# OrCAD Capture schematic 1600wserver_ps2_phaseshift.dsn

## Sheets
1 PAGE3: size C
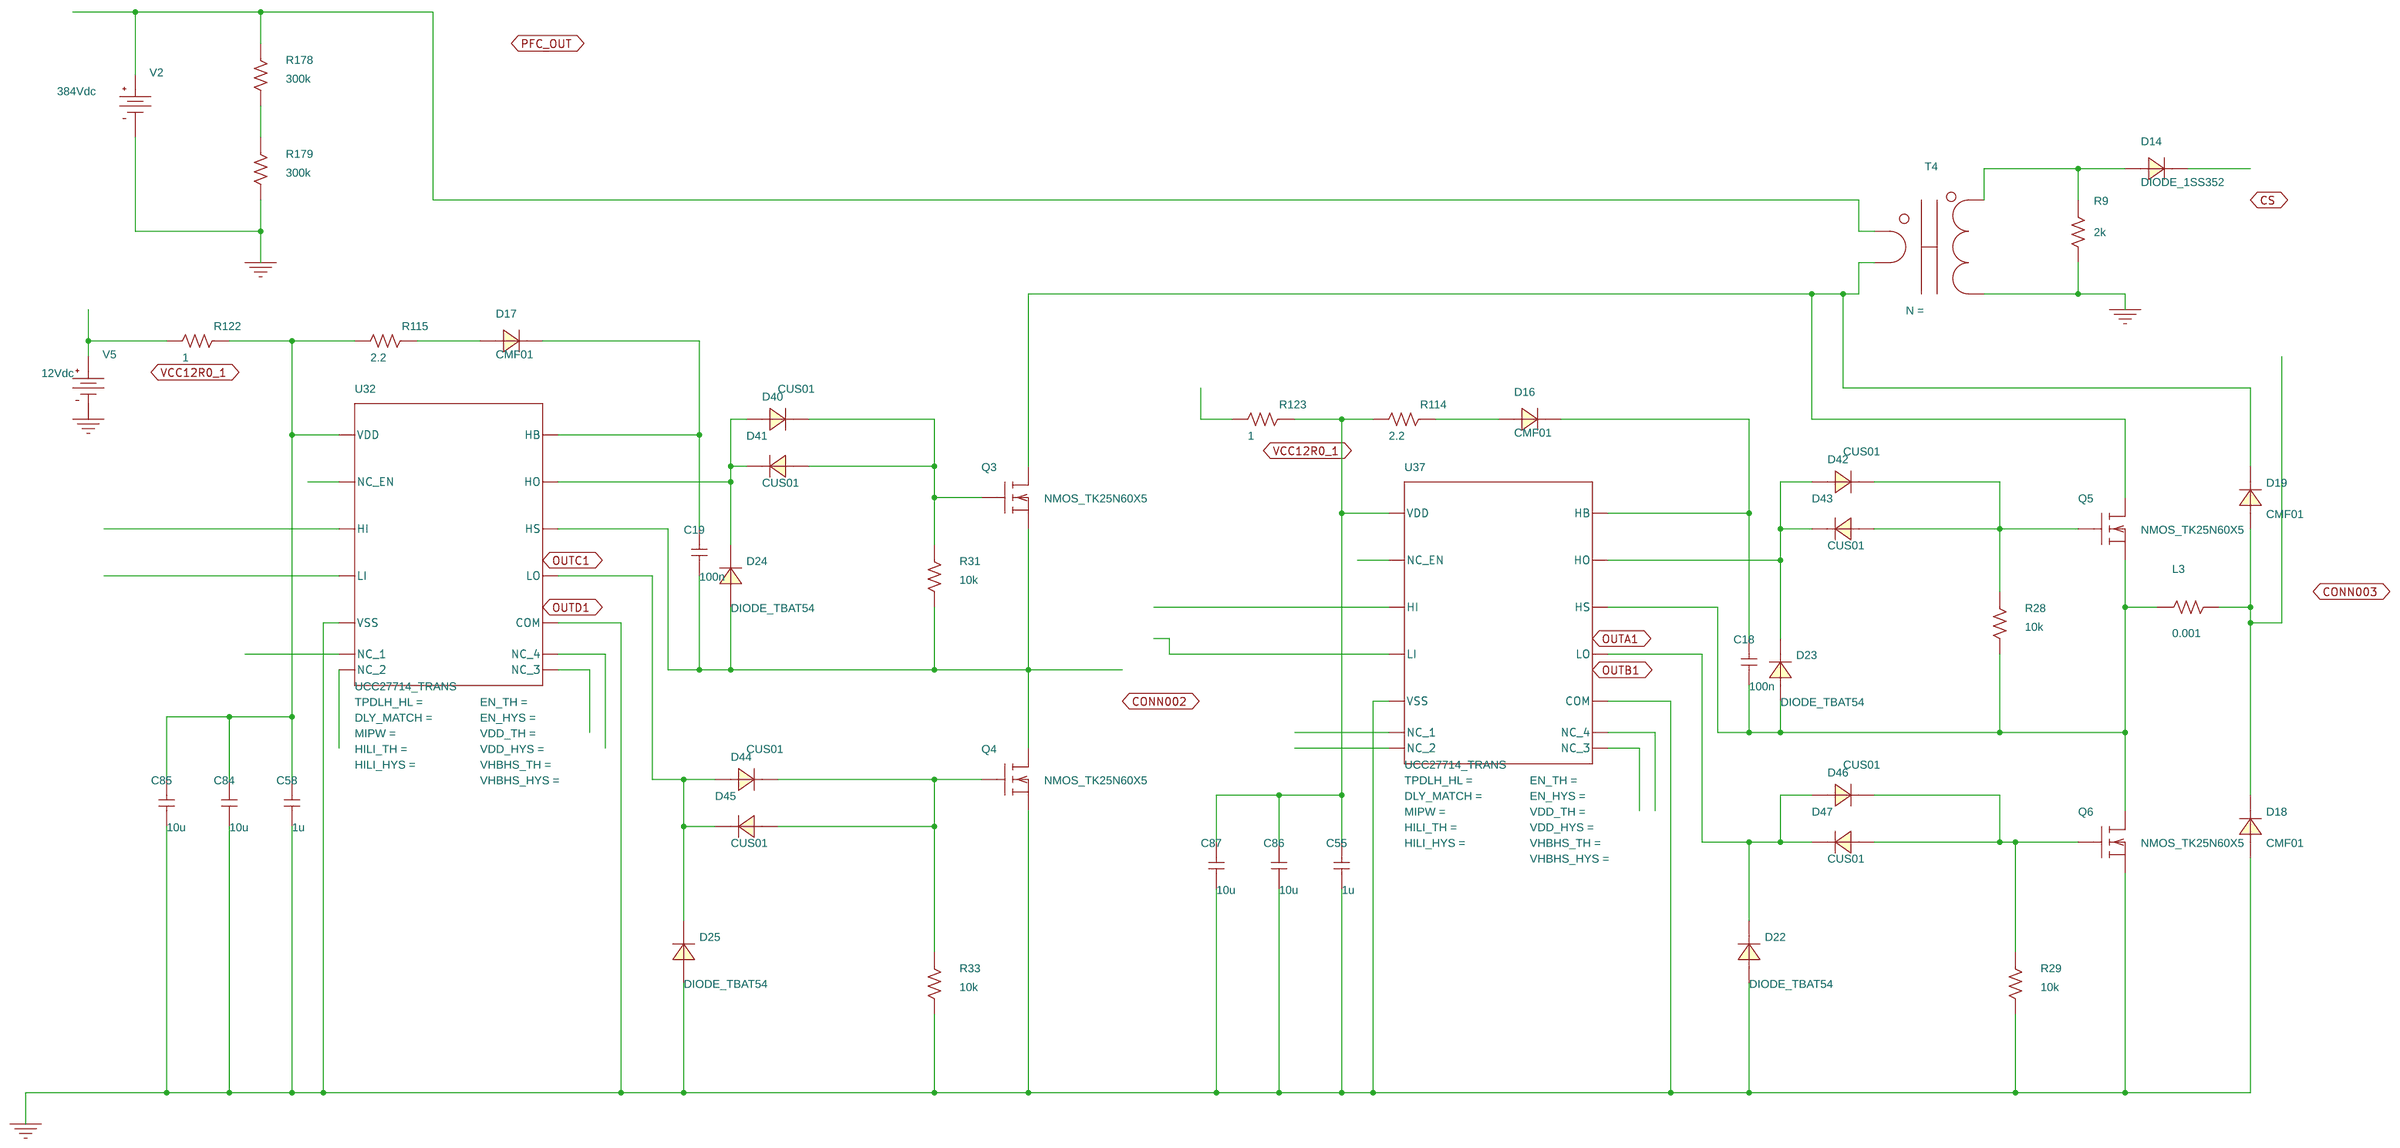
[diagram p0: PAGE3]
2 PAGE2: size C
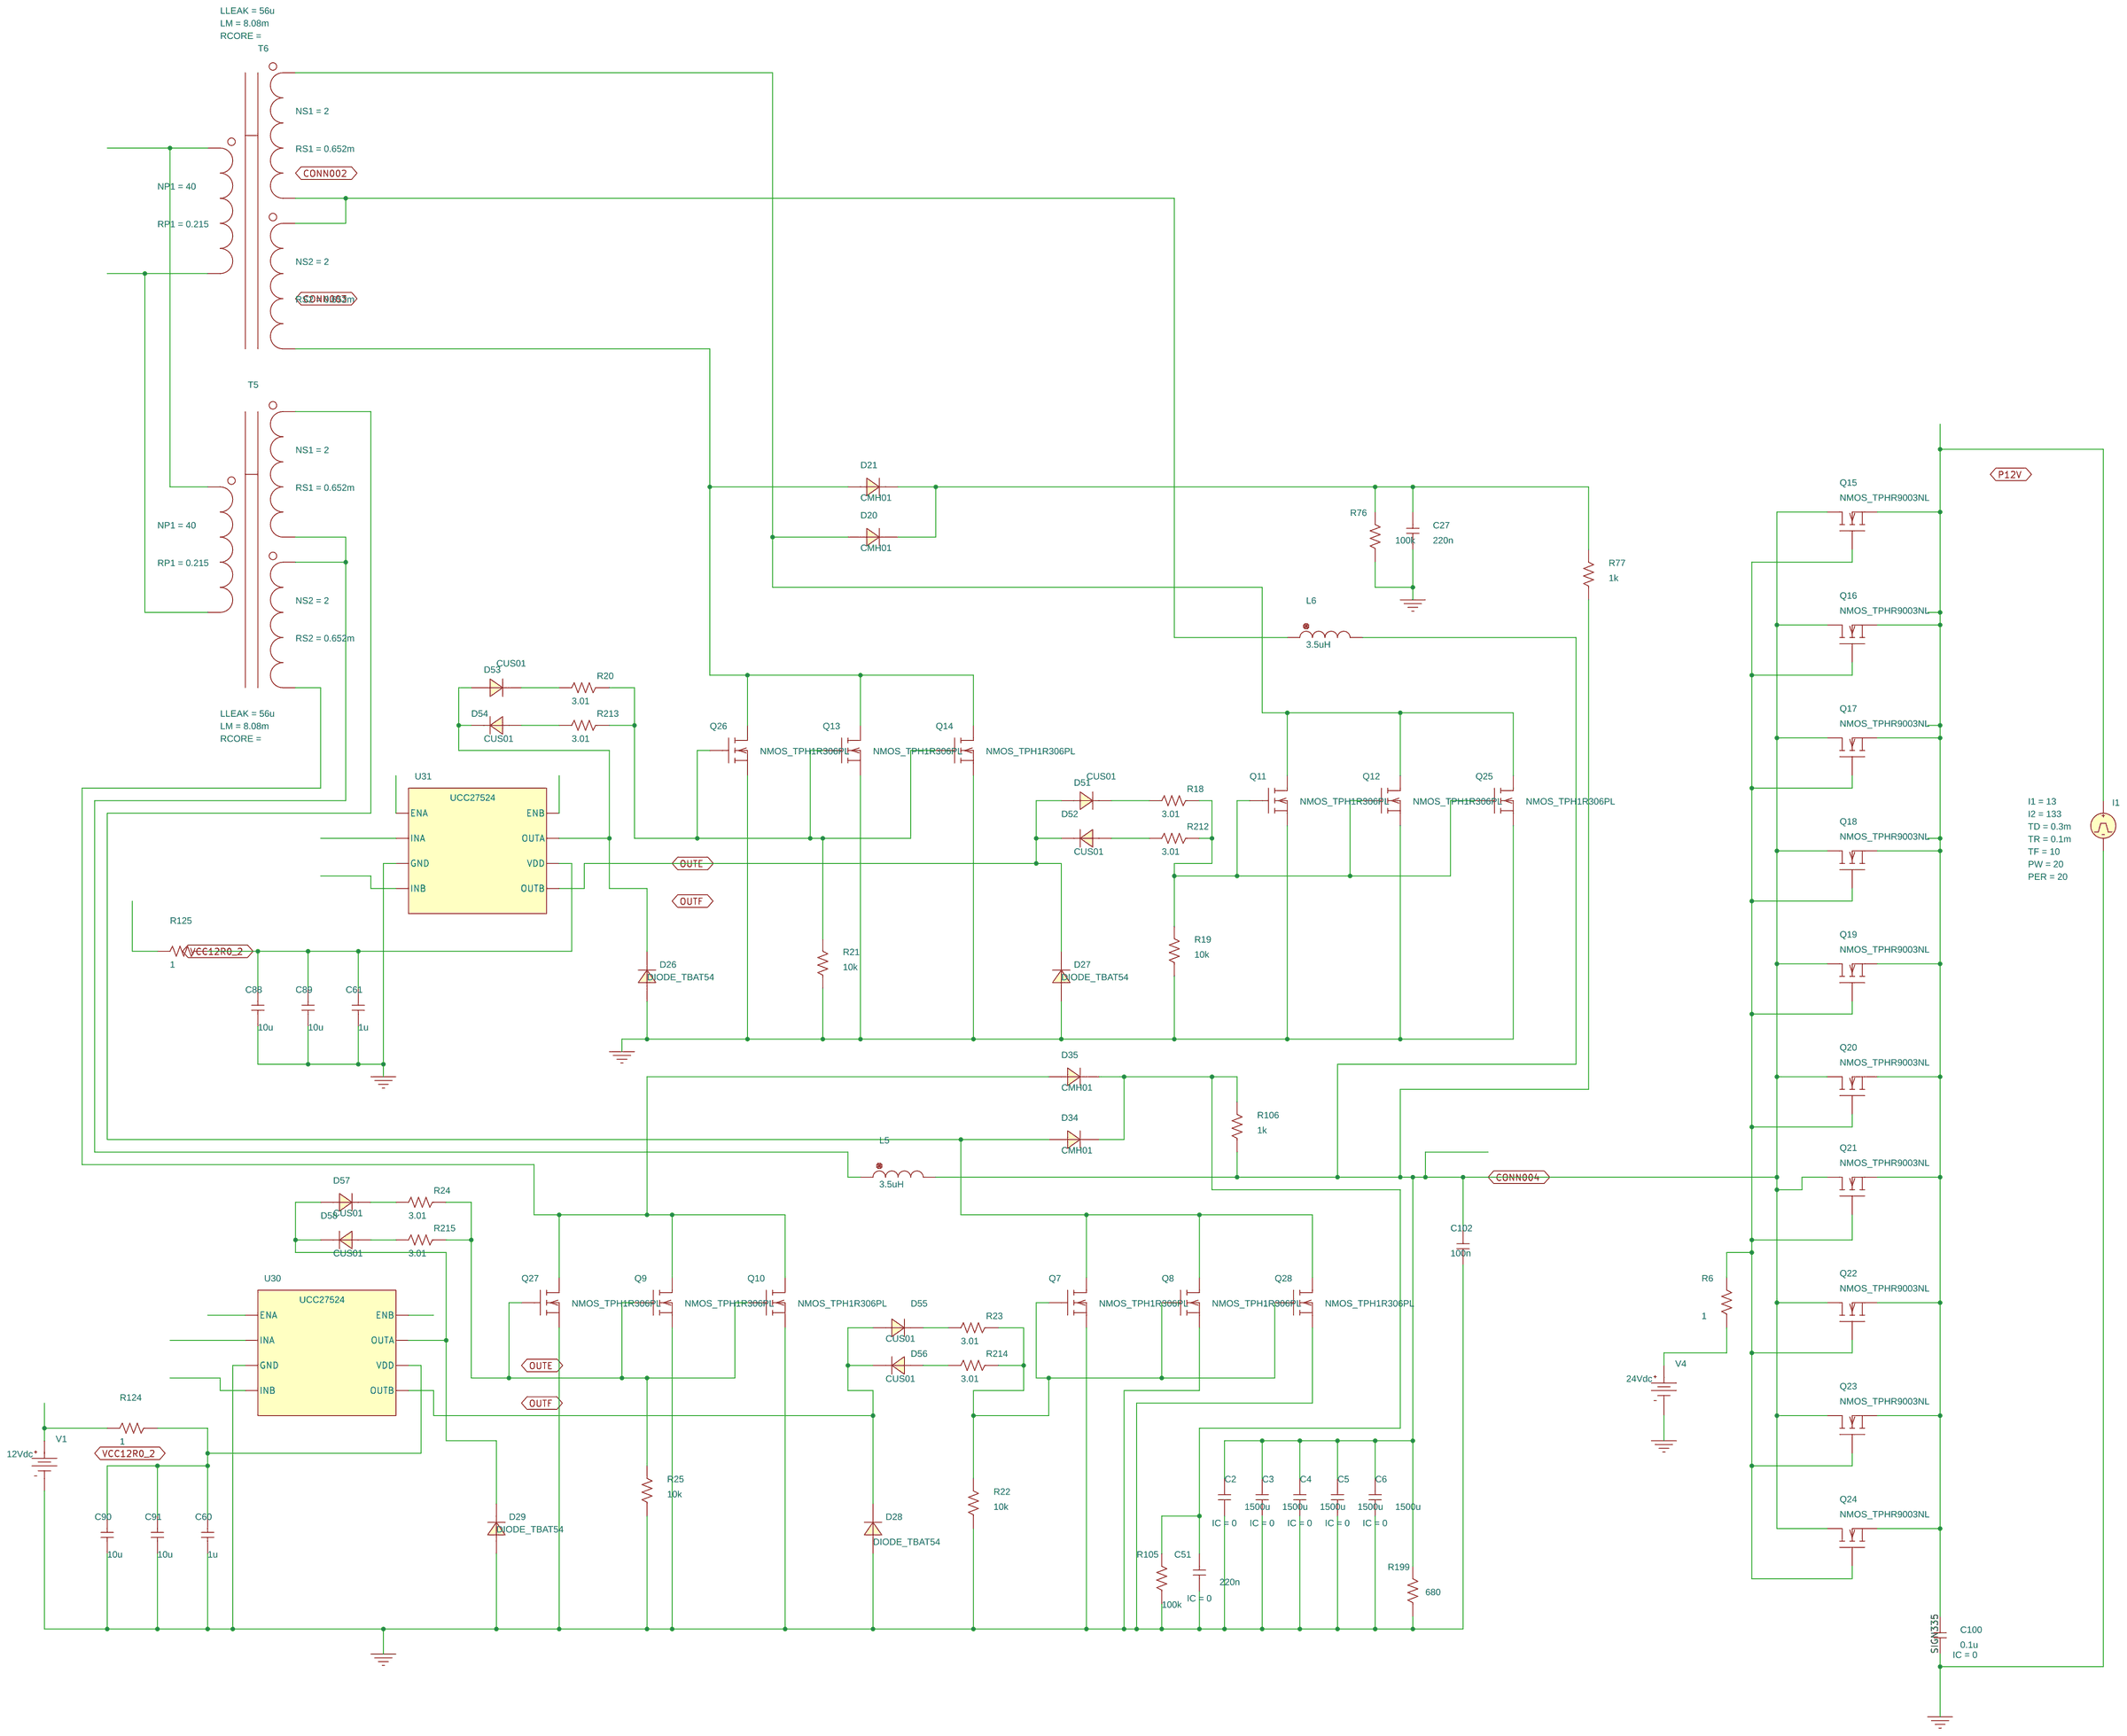
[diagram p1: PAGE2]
3 PAGE1: size C
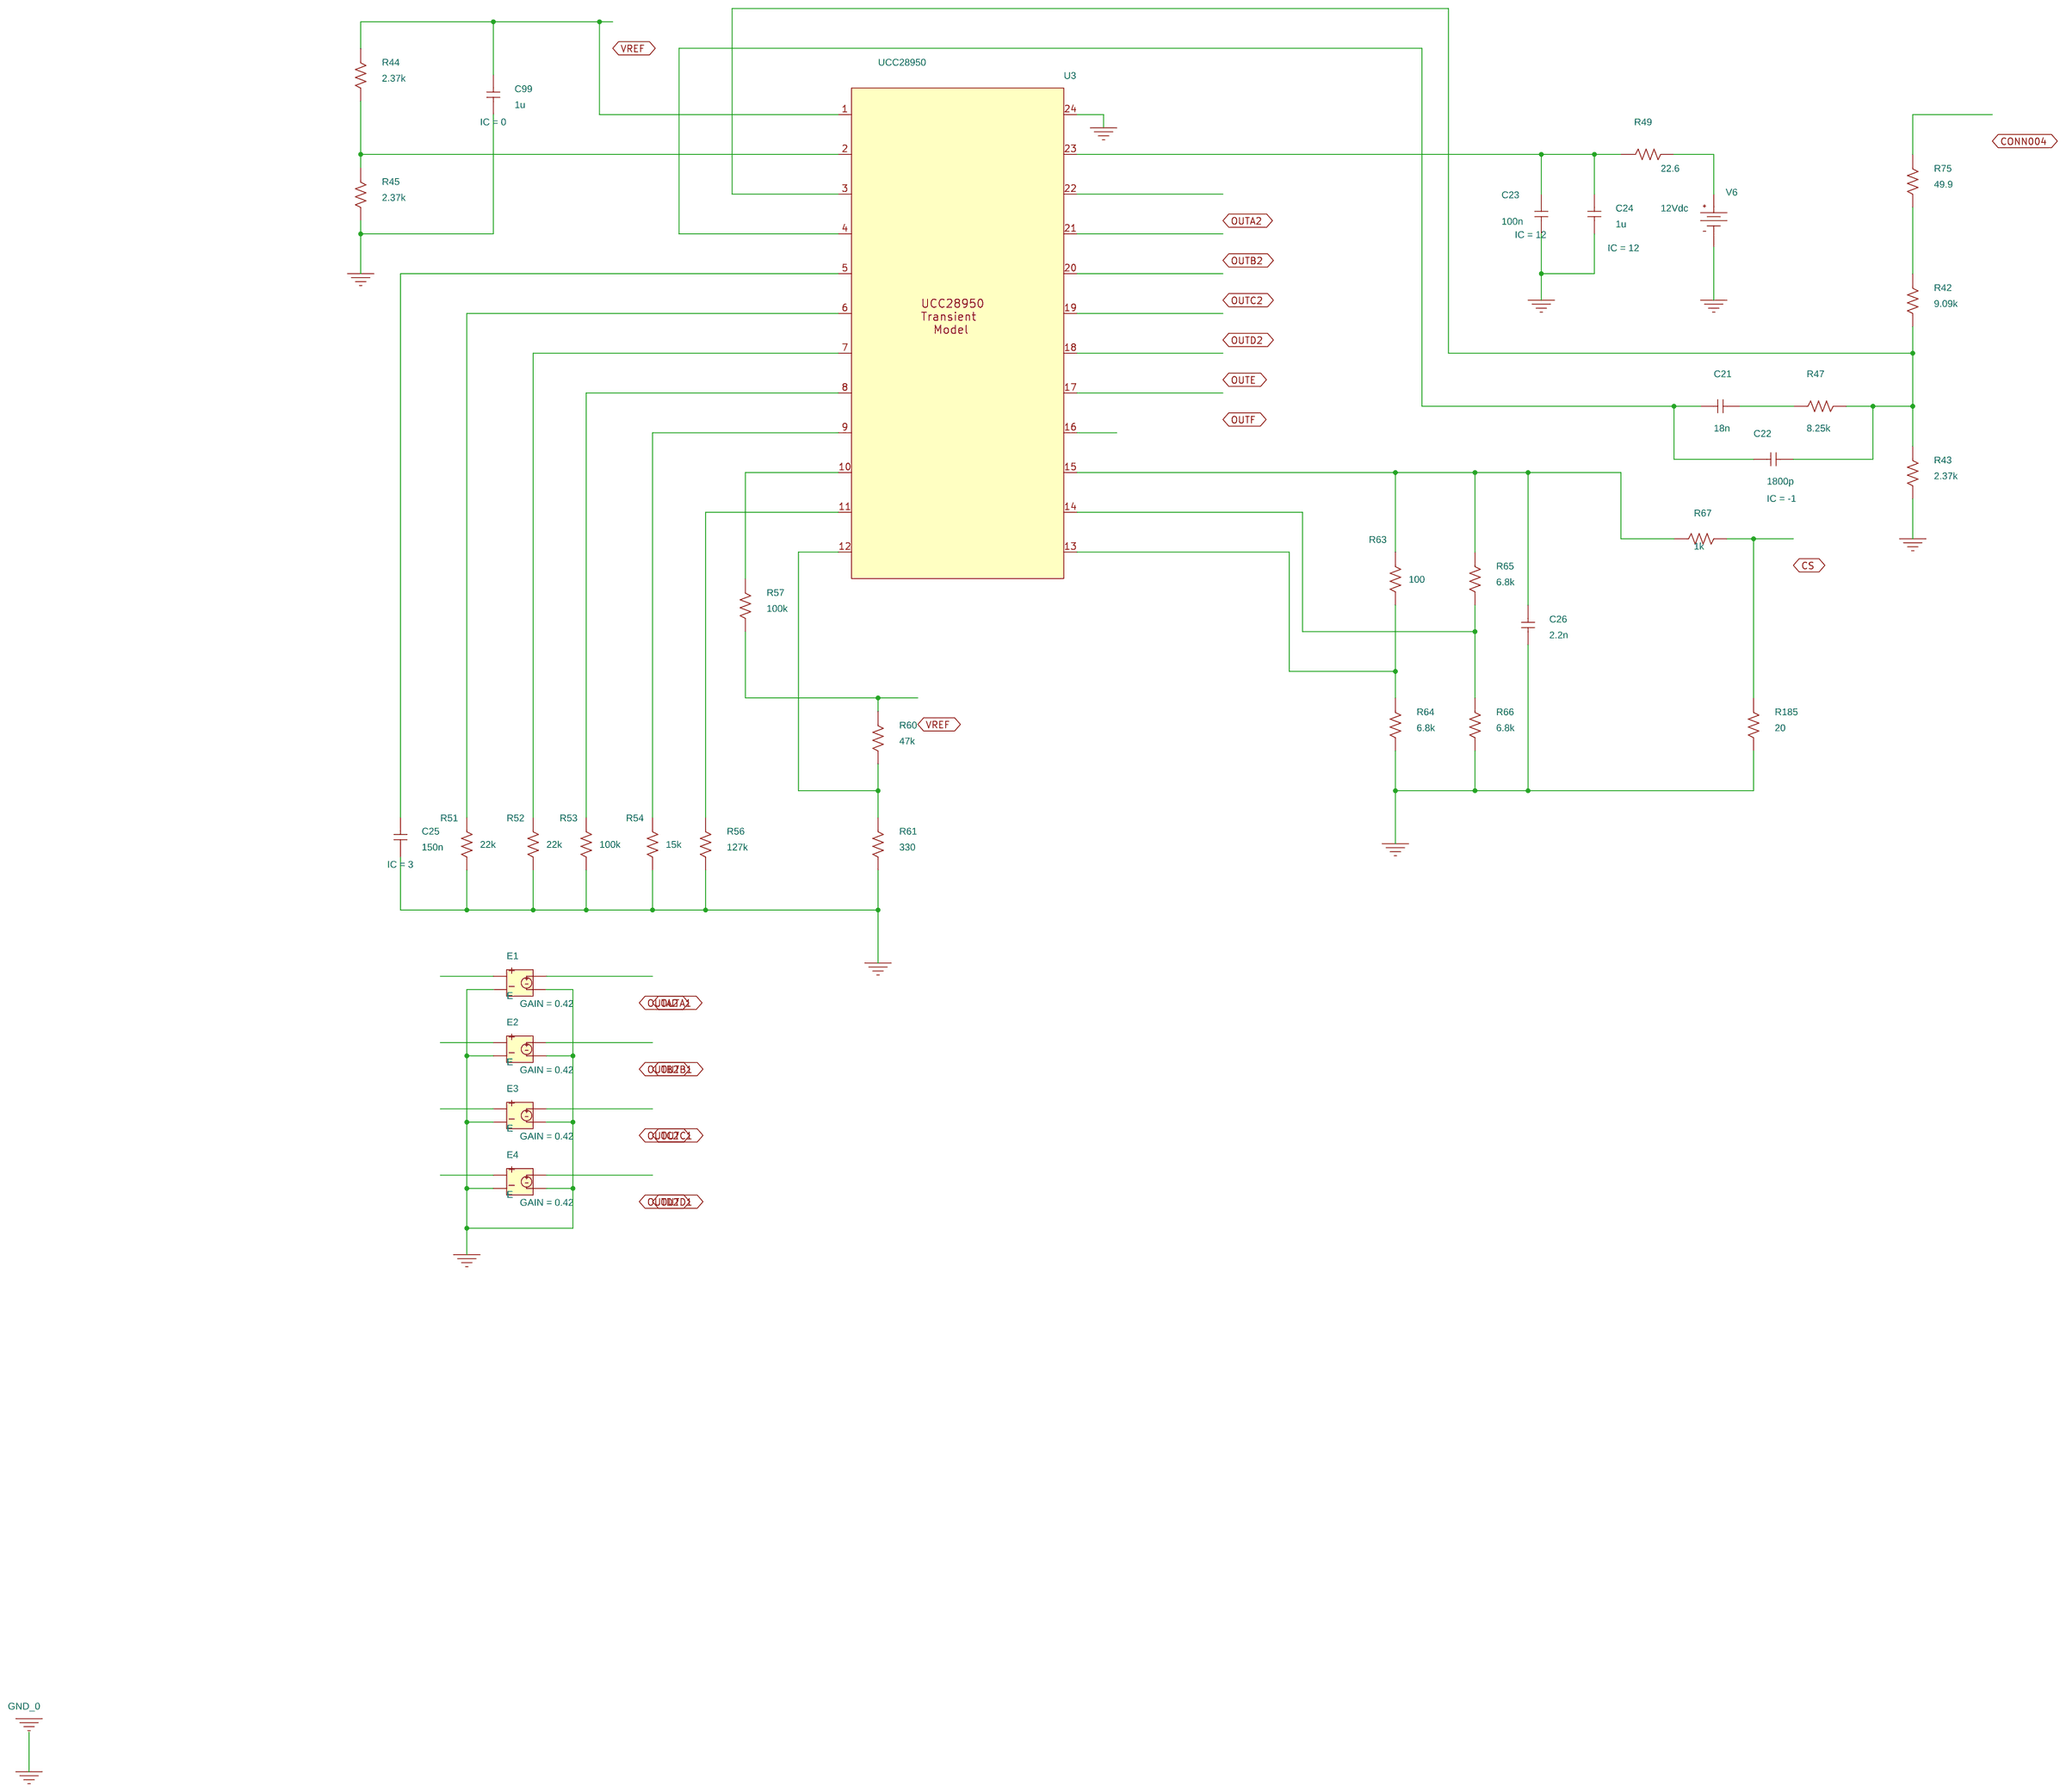
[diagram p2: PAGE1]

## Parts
sheet PAGE1
C21  18n  [RAD/CK05]
C22  1800p  [RAD/CK05]
C23  100n  [RAD/CK05]
C24  1u  [RAD/CK05]
C25  150n  [RAD/CK05]
C26  2.2n  [RAD/CK05]
C99  1u  [RAD/CK05]
E1  E
E2  E
E3  E
E4  E
R42  9.09k  [AX/RC05]
R43  2.37k  [AX/RC05]
R44  2.37k  [AX/RC05]
R45  2.37k  [AX/RC05]
R47  8.25k  [AX/RC05]
R49  22.6  [AX/RC05]
R51  22k  [AX/RC05]
R52  22k  [AX/RC05]
R53  100k  [AX/RC05]
R54  15k  [AX/RC05]
R56  127k  [AX/RC05]
R57  100k  [AX/RC05]
R60  47k  [AX/RC05]
R61  330  [AX/RC05]
R63  100  [AX/RC05]
R64  6.8k  [AX/RC05]
R65  6.8k  [AX/RC05]
R66  6.8k  [AX/RC05]
R67  1k  [AX/RC05]
R75  49.9  [AX/RC05]
R185  20  [AX/RC05]
U3  UCC28950
V6  VDC
sheet PAGE2
C2  1500u  [RAD/CK05]
C3  1500u  [RAD/CK05]
C4  1500u  [RAD/CK05]
C5  1500u  [RAD/CK05]
C6  1500u  [RAD/CK05]
C27  220n  [RAD/CK05]
C51  220n  [RAD/CK05]
C60  1u  [RAD/CK05]
C61  1u  [RAD/CK05]
C88  10u  [RAD/CK05]
C89  10u  [RAD/CK05]
C90  10u  [RAD/CK05]
C91  10u  [RAD/CK05]
C100  0.1u  [RAD/CK05]
C102  100n  [RAD/CK05]
D20  CMH01
D21  CMH01
D26  DIODE_TBAT54
D27  DIODE_TBAT54
D28  DIODE_TBAT54
D29  DIODE_TBAT54
D34  CMH01
D35  CMH01
D51  CUS01
D52  CUS01
D53  CUS01
D54  CUS01
D55  CUS01
D56  CUS01
D57  CUS01
D58  CUS01
I1  IPULSE
L5  3.5uH  [DISC/.350x.175/LS.200x.100/.034]
L6  3.5uH  [DISC/.350x.175/LS.200x.100/.034]
Q7  NMOS_TPH1R306PL
Q8  NMOS_TPH1R306PL
Q9  NMOS_TPH1R306PL
Q10  NMOS_TPH1R306PL
Q11  NMOS_TPH1R306PL
Q12  NMOS_TPH1R306PL
Q13  NMOS_TPH1R306PL
Q14  NMOS_TPH1R306PL
Q15  NMOS_TPHR9003NL
Q16  NMOS_TPHR9003NL
Q17  NMOS_TPHR9003NL
Q18  NMOS_TPHR9003NL
Q19  NMOS_TPHR9003NL
Q20  NMOS_TPHR9003NL
Q21  NMOS_TPHR9003NL
Q22  NMOS_TPHR9003NL
Q23  NMOS_TPHR9003NL
Q24  NMOS_TPHR9003NL
Q25  NMOS_TPH1R306PL
Q26  NMOS_TPH1R306PL
Q27  NMOS_TPH1R306PL
Q28  NMOS_TPH1R306PL
R6  1  [AX/RC05]
R18  3.01  [AX/RC05]
R19  10k  [AX/RC05]
R20  3.01  [AX/RC05]
R21  10k  [AX/RC05]
R22  10k  [AX/RC05]
R23  3.01  [AX/RC05]
R24  3.01  [AX/RC05]
R25  10k  [AX/RC05]
R76  100k  [AX/RC05]
R77  1k  [AX/RC05]
R105  100k  [AX/RC05]
R106  1k  [AX/RC05]
R124  1  [AX/RC05]
R125  1  [AX/RC05]
R199  680  [AX/RC05]
R212  3.01  [AX/RC05]
R213  3.01  [AX/RC05]
R214  3.01  [AX/RC05]
R215  3.01  [AX/RC05]
T5  XFOR_1P2S
T6  XFOR_1P2S
U30  UCC27524
U31  UCC27524
V1  VDC
V4  VDC
sheet PAGE3
C18  100n  [RAD/CK05]
C19  100n  [RAD/CK05]
C55  1u  [RAD/CK05]
C58  1u  [RAD/CK05]
C84  10u  [RAD/CK05]
C85  10u  [RAD/CK05]
C86  10u  [RAD/CK05]
C87  10u  [RAD/CK05]
D14  DIODE_1SS352
D16  CMF01
D17  CMF01
D18  CMF01
D19  CMF01
D22  DIODE_TBAT54
D23  DIODE_TBAT54
D24  DIODE_TBAT54
D25  DIODE_TBAT54
D40  CUS01
D41  CUS01
D42  CUS01
D43  CUS01
D44  CUS01
D45  CUS01
D46  CUS01
D47  CUS01
L3  0.001  [AX/RC05]
Q3  NMOS_TK25N60X5
Q4  NMOS_TK25N60X5
Q5  NMOS_TK25N60X5
Q6  NMOS_TK25N60X5
R9  2k  [AX/RC05]
R28  10k  [AX/RC05]
R29  10k  [AX/RC05]
R31  10k  [AX/RC05]
R33  10k  [AX/RC05]
R114  2.2  [AX/RC05]
R115  2.2  [AX/RC05]
R122  1  [AX/RC05]
R123  1  [AX/RC05]
R178  300k  [AX/RC05]
R179  300k  [AX/RC05]
T4  XFOR_CS
U32  UCC27714_TRANS
U37  UCC27714_TRANS
V2  VDC
V5  VDC

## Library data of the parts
C18 C19 C21 C26 C27 C55 C58 C60 C61 C84-C91 C102 = C_v3
C22 = C_v3: IC: -1
C23 C24 = C_v3: IC: 12
C25 = C_v3: IC: 3
C2-C6 C51 C99 C100 = C_v3: IC: 0
E1-E4 = E: GAIN: 0.42
L3 R6 R9 R18-R25 R28 R29 R31 R33 R42-R45 R47 R49 R51-R54 R56 R57 R60 R61 R63-R67 R75-R77 R105 R106 R114 R115 R122-R125 R178 R179 R185 R199 R212-R215 = R_v3
U3 = UCC28950
V1 V5 V6 = VDC: DC: 12Vdc
D20 D21 D34 D35 = CMH01
D22-D29 = DIODE_TBAT54
D40-D47 D51-D58 = CUS01
I1 = IPULSE: I1: 13; I2: 133; PER: 20; PW: 20; TD: 0.3m; TF: 10; TR: 0.1m
L5 L6 = L_v2
Q7-Q14 Q25-Q28 = NMOS_TPH1R306PL
Q15-Q24 = NMOS_TPHR9003NL
T5 T6 = XFOR_1P2S: LLEAK: 56u; LM: 8.08m; NP1: 40; NS1: 2; NS2: 2; PSpiceTemplate: X^@REFDES %P1A %P1B %S1A %S1B %S2A %S2B @MODEL PARAMS:  ?NP1|NP1=@NP1||NP1=10|  ?NS1|NS1=@NS1||NS1=1|  ?NS2|NS2=@NS2||NS2=1|  ?RP1|RP1=@RP1||RP1=0.001|  ?RS1|RS1=@RS1||RS1=0.001|  ?RS2|RS2=@RS2||RS2=0.001|  ?LLEAK|LLEAK=@LLEAK||LLEAK=100e-9|  ?LM|LM=@LM||LM=0.01| ?RCORE|RCORE=@RCORE||RCORE=100e3|; RP1: 0.215; RS1: 0.652m; RS2: 0.652m
U30 = UCC27524
U31 = UCC27524_1
V4 = VDC: DC: 24Vdc
D14 = DIODE_1SS352
D16-D19 = CMF01
Q3-Q6 = NMOS_TK25N60X5
T4 = XFOR_CS
U32 = UCC27714_TRANS_1
U37 = UCC27714_TRANS
V2 = VDC: DC: 384Vdc

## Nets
P12V: C100.1 I1.1(+) Q15.0(s) Q16.0(s) Q17.0(s) Q18.0(s) Q19.0(s) Q20.0(s) Q21.0(s) Q22.0(s) Q23.0(s) Q24.0(s)
VCC12R0_1: R122.2 R123.2 V5.0(+)
VCC12R0_2: R124.2 R125.2 V1.0(+)
0: C2.2 C3.2 C4.2 C5.2 C6.2 C23.2 C24.2 C25.2 C26.1 C27.1 C51.2 C55.1 C58.1 C60.1 C61.1 C84.1 C85.1 C86.1 C87.1 C88.1 C89.1 C90.1 C91.1 C99.2 C100.2 C102.1 D18.1 D22.1 D25.1 D26.1 D27.1 D28.1 D29.1 E1.2 E1.4 E2.2 E2.4 E3.2 E3.4 E4.2 E4.4 I1.2(-) Q4.0(s) Q6.0(s) Q7.0(s) Q8.0(s) Q9.0(s) Q10.0(s) Q11.0(s) Q12.0(s) Q13.0(s) Q14.0(s) Q25.0(s) Q26.0(s) Q27.0(s) Q28.0(s) R9.2 R19.1 R21.1 R22.1 R25.1 R29.2 R33.2 R43.2 R45.2 R51.2 R52.2 R53.2 R54.2 R56.2 R61.2 R64.2 R66.2 R76.1 R105.1 R179.2 R185.2 R199.1 T4.4(S1B) U3.24(GND) U30.GND U31.GND U32.COM U32.VSS U37.COM U37.VSS V1.1(-) V2.1(-) V4.1(-) V5.1(-) V6.1(-)
CONN002: C19.1 D24.1 Q3.0(s) Q4.2(d) R31.2 T5.1(P1A) T6.1(P1A) U32.HS
CONN003: D18.2 D19.1 L3.2 T5.2(P1B) T6.2(P1B)
CONN004: C2.1 C3.1 C4.1 C5.1 C6.1 C102.2 L5.2 L6.2 Q15.2(d) Q16.2(d) Q17.2(d) Q18.2(d) Q19.2(d) Q20.2(d) Q21.2(d) Q22.2(d) Q23.2(d) Q24.2(d) R75.1 R77.1 R106.1 R199.2
CS: D14.2 R67.2 R185.1
OUTA1: E1.3 U37.HI
OUTA2: E1.1 U3.22(OUTA)
OUTB1: E2.3 U37.LI
OUTB2: E2.1 U3.21(OUTB)
OUTC1: E3.3 U32.HI
OUTC2: E3.1 U3.20(OUTC)
OUTD1: E4.3 U32.LI
OUTD2: E4.1 U3.19(OUTD)
OUTE: U3.18(OUTE) U30.INA U31.INA
OUTF: U3.17(OUTF) U30.INB U31.INB
PFC_OUT: R178.1 T4.1(P1A) V2.0(+)
VREF: C99.1 R44.1 R57.2 R60.1 U3.1(VREF)
N39747: C22.1 R42.2 R43.1 R47.2 U3.3(EAM)
N39759: C21.2 C22.2 U3.4(COMP)
N39771: C26.2 R63.1 R65.1 R67.1 U3.15(CS)
N40171: R65.2 R66.1 U3.14(ADEL)
N40207: R63.2 R64.1 U3.13(ADELEF)
N40235: R51.1 U3.6(DELAB)
N40333: R52.1 U3.7(DELCD)
N40557: R60.2 R61.1 U3.12(DCM)
N40781: R54.1 U3.9(TMIN)
N47463: D21.1 Q13.2(d) Q14.2(d) Q26.2(d) T6.^(S2B)
N47471: C27.2 D20.2 D21.2 R76.2 R77.2
N47761: Q15.1(g) Q16.1(g) Q17.1(g) Q18.1(g) Q19.1(g) Q20.1(g) Q21.1(g) Q22.1(g) Q23.1(g) Q24.1(g) R6.2
N47913: D20.1 Q11.2(d) Q12.2(d) Q25.2(d) T6.3(S1A)
N48253: D26.2 D53.2 D54.1 U31.OUTA
N48267: Q13.1(g) Q14.1(g) Q26.1(g) R20.1 R21.2 R213.1
N48783: D35.1 Q9.2(d) Q10.2(d) Q27.2(d) T5.^(S2B)
N48833: L5.1 T5.4(S1B) T5.5(S2A)
N48841: D27.2 D51.2 D52.1 U31.OUTB
N48855: Q11.1(g) Q12.1(g) Q25.1(g) R18.1 R19.2 R212.1
N48885: D34.1 Q7.2(d) Q8.2(d) Q28.2(d) T5.3(S1A)
N49439: C61.2 C88.2 C89.2 R125.1 U31.VDD
N49921: C51.1 D34.2 D35.2 R105.2 R106.2
N50381: D29.2 D57.1 D58.2 U30.OUTA
N50397: Q9.1(g) Q10.1(g) Q27.1(g) R24.1 R25.2 R215.1
N51051: D28.2 D55.1 D56.2 U30.OUTB
N51139: R6.1 V4.0(+)
N51225: Q7.1(g) Q8.1(g) Q28.1(g) R22.2 R23.1 R214.1
N51631: C60.2 C90.2 C91.2 R124.1 U30.VDD
N99611: D55.2 R23.2
N99615: D56.1 R214.2
N123337: D19.2 Q3.2(d) Q5.2(d) T4.2(P1B)
N123457: C58.2 C84.2 C85.2 R115.2 R122.1 U32.VDD
N123483: C19.2 D17.2 U32.HB
N123665: D40.1 D41.2 Q3.1(g) R31.1
N123673: C55.2 C86.2 C87.2 R114.2 R123.1 U37.VDD
N123699: C18.2 D16.2 U37.HB
N123855: D23.2 D42.2 D43.1 U37.HO
N123873: D42.1 D43.2 Q5.1(g) R28.1
N124131: D25.2 D44.2 D45.1 U32.LO
N124259: C18.1 D23.1 L3.1 Q5.0(s) Q6.2(d) R28.2 U37.HS
N124347: D22.2 D46.2 D47.1 U37.LO
N124571: D44.1 D45.2 Q4.1(g) R33.1
N124713: D46.1 D47.2 Q6.1(g) R29.1
N126734: D24.2 D40.2 D41.1 U32.HO
N141698: D16.1 R114.1
N891520: L6.1 T6.4(S1B) T6.5(S2A)
N949463: R57.1 U3.10(RT)
N950129: R56.1 U3.11(RSUM)
N950657: R53.1 U3.8(DELEF)
N951018: C25.1 U3.5(SSEN)
N951567: R44.2 R45.1 U3.2(EAP)
N954776: C23.1 C24.1 R49.1 U3.23(VDD)
N958236: D14.1 R9.1 T4.3(S1A)
N993468: D17.1 R115.1
N993582: R178.2 R179.1
N993700: D54.2 R20.2
N993706: D53.1 R213.2
N993710: D52.2 R18.2
N993714: D51.1 R212.2
N993754: D57.2 R24.2
N993758: D58.1 R215.2
N994547: C21.1 R47.1
N994551: R42.1 R75.2
N1000861: R49.2 V6.0(+)

Not connected (* = marked no-connect by the designer): U3 16(SYNC); U30 ENA ENB; U31 ENA ENB; U32 NC_1 NC_2 NC_3 NC_4 NC_EN; U37 NC_1 NC_2 NC_3 NC_4 NC_EN
